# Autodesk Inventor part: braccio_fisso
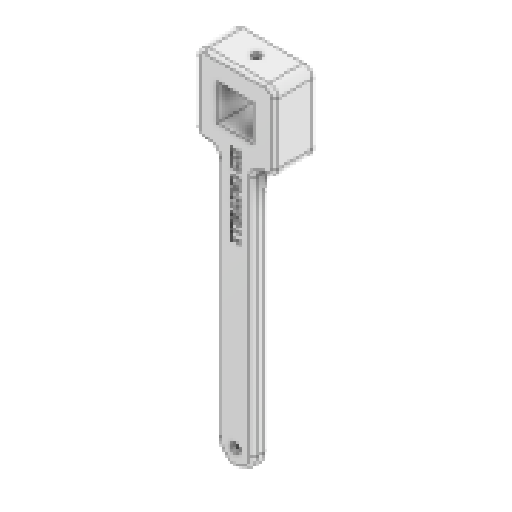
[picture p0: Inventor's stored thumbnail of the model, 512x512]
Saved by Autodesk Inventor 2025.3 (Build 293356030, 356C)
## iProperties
Created: 2025-09
Part Number: braccio_fisso
Material: Plastica ABS
Document SubType Name: Modeling
Designer: Ryzen5700u
Density: 1.06 g/cm^3
Appearance: Liscia - Bianco
Author: Ryzen5700u
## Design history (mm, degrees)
sketch "Schizzo1"
  geometry: L1 (-10.05, -10.05)-(10.05, -10.05); L2 (10.05, -10.05)-(10.05, 10.05); L3 (10.05, 10.05)-(-10.05, 10.05); L4 (-10.05, 10.05)-(-10.05, -10.05); L5 (-10.05, -10.05)-(10.05, 10.05); L6 (10.05, -10.05)-(-10.05, 10.05); L7 (-22, -22)-(22, -22); L8 (22, -22)-(22, 22); L9 (22, 22)-(-22, 22); L10 (-22, 22)-(-22, -22); L11 (-22, -22)-(22, 22); L12 (22, -22)-(-22, 22); L13 (-10, -22)-(10, -22); L14 (10, -22)-(10, -172); L15 (10, -172)-(-10, -172); L16 (-10, -172)-(-10, -22); 2 further points
  constraints: 32 end point, 6 parallel, 4 midpoint, 3 horizontal, 3 perpendicular, 1 point on line
  dimensions: "d0" = 20.1 distance of L3.end L2.end; "d1" = 20.1 distance of L2.end L1.end; "d2" = 44 distance of L9.end L8.end; "d3" = 44 distance of L7.end L8.end; "d4" = 150 distance of L13.end L14.end
extrude "Estrusione1" new body sketch "Schizzo1" distance "d5" = 8; taper "d6" = 0 deg
sketch "Schizzo2"
  geometry: L1 (22, -22)-(10, -22) reference; L2 (22, 22)-(22, -22) reference; L3 (-22, 22)-(22, 22) reference; L4 (-22, -22)-(-22, 22) reference; L5 (-10, -22)-(-22, -22) reference; L6 (-10, -172)-(-10, -22) reference; L7 (10, -172)-(-10, -172) reference; L8 (10, -22)-(10, -172) reference; L9 (10.05, -10.05)-(10.05, 10.05) reference; L10 (-10.05, -10.05)-(10.05, -10.05) reference; L11 (-10.05, 10.05)-(-10.05, -10.05) reference; L12 (10.05, 10.05)-(-10.05, 10.05) reference; L13 (10, -22)-(-10, -22); 1 further point
  constraints: 2 end point, 1 horizontal
extrude "Estrusione2" join sketch "Schizzo2" distance "d7" = 15; taper "d8" = 0 deg
sketch "Schizzo3"
  geometry: L1 (44, 23)-(44, 0) reference; L2 (44, 23)-(0, 23) reference; L3 (44, 0)-(0, 23); L4 (0, 0)-(0, 23) reference; L5 (0, 23)-(0, 0); L6 (0, 0)-(45.029, 22.647); 2 further points
  constraints: 6 end point, 2 point on line, 1 collinear
hole "Foro1" sketch "Schizzo3" at (22.424, 11.278) diameter "d9" = 4.5; stored, may be unused: countersink angle "d13" = 90 deg, drill point angle "d15" = 118 deg; dims "d10" = 6, "d11" = 10, "d12" = 5.7, "d14" = 64.25
fillet "Raccordo1" dims "d16" = 5
sketch "Schizzo6"
  geometry: L1 (2.697, -16.966)-(2.697, -70.179); L2 (2.697, -70.179)-(-3.392, -70.179); L3 (-3.392, -70.179)-(-3.392, -16.966); L4 (-3.392, -16.966)-(2.697, -16.966); 1 further point
  constraints: 2 other
extrude "Estrusione5" cut sketch "Schizzo6" distance "d23" = 0.2; taper "d24" = 0 deg
fillet "Raccordo3" dims "d25" = 15
fillet "Raccordo6" dims "d28" = 10
sketch "Schizzo7"
  geometry: L1 (10, -162)-(10, -27) reference; L2 (15, -22)-(17, -22) reference; L3 (22, -17)-(22, 17) reference; L4 (17, 22)-(-17, 22) reference; L5 (-22, 17)-(-22, -17) reference; L6 (-17, -22)-(-15, -22) reference; L7 (-10, -27)-(-10, -162) reference; L8 (-1.448, -59.863)-(-2.4, -59.863) reference; L9 (-2.4, -59.863)-(-2.4, -56.528) reference; L10 (-2.4, -56.528)-(2.6, -56.528) reference; L11 (2.6, -56.528)-(2.6, -57.784) reference; L12 (2.6, -57.784)-(-1.448, -57.784) reference; L13 (-1.448, -57.784)-(-1.448, -59.863) reference; L14 (-2.4, -51.743)-(-2.4, -48.364) reference; L15 (-2.4, -48.364)-(2.6, -48.364) reference; L16 (2.6, -48.364)-(2.6, -51.743) reference; L17 (2.6, -51.743)-(1.647, -51.743) reference; L18 (1.647, -51.743)-(1.647, -49.612) reference; L19 (1.647, -49.612)-(0.768, -49.612) reference; L20 (0.768, -49.612)-(0.768, -51.577) reference; L21 (0.768, -51.577)-(-0.184, -51.577) reference; L22 (-0.184, -51.577)-(-0.184, -49.612) reference; L23 (-0.184, -49.612)-(-1.448, -49.612) reference; L24 (-1.448, -49.612)-(-1.448, -51.743) reference; L25 (-1.448, -51.743)-(-2.4, -51.743) reference; L26 (-2.105, -39.527)-(-0.913, -39.527) reference; L27 (-0.913, -39.527)-(-0.913, -39.64) reference; L28 (2.352, -43.311)-(1.21, -43.311) reference; L29 (1.21, -43.311)-(1.21, -43.202) reference; L30 (-2.4, -35.807)-(-2.4, -34.551) reference; L31 (-2.4, -34.551)-(2.6, -36.241) reference; L32 (2.6, -36.241)-(2.6, -37.61) reference; L33 (2.6, -37.61)-(-2.4, -39.3) reference; L34 (-2.4, -39.3)-(-2.4, -38.007) reference; L35 (-2.4, -38.007)-(-1.379, -37.695) reference; L36 (-1.379, -37.695)-(-1.379, -36.123) reference; L37 (-1.379, -36.123)-(-2.4, -35.807) reference; L38 (-2.105, -23.858)-(-0.913, -23.858) reference; L39 (-0.913, -23.858)-(-0.913, -23.972) reference; L40 (2.352, -27.643)-(1.21, -27.643) reference; L41 (1.21, -27.643)-(1.21, -27.533) reference; L42 (-1.529, -19.972)-(-2.4, -19.972) reference; L43 (-2.4, -19.972)-(-2.4, -17.282) reference; L44 (-2.4, -17.282)-(-1.529, -17.282) reference; L45 (-1.529, -17.282)-(-1.529, -17.999) reference; L46 (-1.529, -17.999)-(1.728, -17.999) reference; L47 (1.728, -17.999)-(1.728, -17.282) reference; L48 (1.728, -17.282)-(2.6, -17.282) reference; L49 (2.6, -17.282)-(2.6, -19.972) reference; L50 (2.6, -19.972)-(1.728, -19.972) reference; L51 (1.728, -19.972)-(1.728, -19.255) reference; L52 (1.728, -19.255)-(-1.529, -19.255) reference; L53 (-1.529, -19.255)-(-1.529, -19.972) reference; L54 (-1.529, -23.295)-(-2.4, -23.295) reference; L55 (-2.4, -23.295)-(-2.4, -20.604) reference; L56 (-2.4, -20.604)-(-1.529, -20.604) reference; L57 (-1.529, -20.604)-(-1.529, -21.322) reference; L58 (-1.529, -21.322)-(1.728, -21.322) reference; L59 (1.728, -21.322)-(1.728, -20.604) reference; L60 (1.728, -20.604)-(2.6, -20.604) reference; L61 (2.6, -20.604)-(2.6, -23.295) reference; L62 (2.6, -23.295)-(1.728, -23.295) reference; L63 (1.728, -23.295)-(1.728, -22.578) reference; L64 (1.728, -22.578)-(-1.529, -22.578) reference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; C1 r 15 at (0, -162); A1 r 10 centre (0, -162) between (-10, -162) and (10, -162) reference; A2 r 10 centre (0, -162) between (-10, -162) and (10, -162) reference; A3 r 5 centre (15, -27) between (15, -22) and (10, -27) reference; A4 r 5 centre (17, -17) between (17, -22) and (22, -17) reference; A5 r 5 centre (17, 17) between (22, 17) and (17, 22) reference; A6 r 5 centre (-17, 17) between (-17, 22) and (-22, 17) reference; A7 r 5 centre (-17, -17) between (-22, -17) and (-17, -22) reference; A8 r 5 centre (-15, -27) between (-10, -27) and (-15, -22) reference; 45 further points
  constraints: 1 centre point, 1 coincident, 46 other
  dimensions: "d29" = 30 diameter of C1
extrude "Estrusione6" join sketch "Schizzo7" stored distance "d30" = 10; taper "d31" = 0 deg
sketch "Schizzo8"
  geometry: A1 r 10 centre (0, -162) between (-10, -162) and (10, -162) reference; 4 further points
  constraints: 1 coincident
hole "Foro2" sketch "Schizzo8" at (0, -162) diameter "d32" = 4.5; stored, may be unused: countersink angle "d36" = 90 deg, drill point angle "d38" = 118 deg; dims "d33" = 6, "d34" = 8, "d35" = 4.6, "d37" = 8
sketch "Schizzo9"
  geometry: L1 (4.5, -162)-(2.25, -165.897); L2 (2.25, -165.897)-(-2.25, -165.897); L3 (-2.25, -165.897)-(-4.5, -162); L4 (-4.5, -162)-(-2.25, -158.103); L5 (-2.25, -158.103)-(2.25, -158.103); L6 (2.25, -158.103)-(4.5, -162); C1 r 2.25 at (0, -162) reference; 2 further points
  constraints: 12 end point, 1 coincident, 13 other
  dimensions: "d39" = 4.5 distance of L1.end L2.end
extrude "Estrusione7" cut sketch "Schizzo9" distance "d40" = 3; taper "d41" = 0 deg
fillet "Raccordo7" dims "d42" = 2
fillet "Raccordo8" dims "d43" = 2
sketch "Schizzo10"
  geometry: C1 r 2.25 at (0, -162) reference; 2 further points
  constraints: 1 coincident
hole "Foro3" sketch "Schizzo10" at (0, -162) diameter "d44" = 4.5; stored, may be unused: countersink angle "d48" = 90 deg, drill point angle "d50" = 118 deg; dims "d45" = 6, "d46" = 8, "d47" = 3.4, "d49" = 8
node "Solido1"
node "Linea chiusa proiettata1"
node "Linea chiusa proiettata2"
